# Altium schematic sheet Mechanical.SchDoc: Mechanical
size A4; Date: Not used; ApprovedBy: Not used; CheckedBy: Not used; Author: Not used; CompanyName: STMicroelectronics; DrawnBy: Not used; Engineer: Not used; Organization: Not used; Address1: Not used; Address2: Not used; Address3: Not used; Address4: Not used; DocumentNumber: Not used; Revision: Not used; SheetNumber: 7; SheetTotal: 7
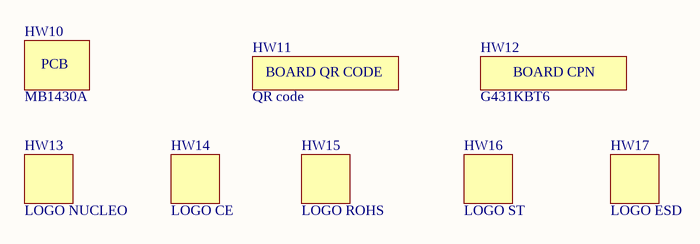
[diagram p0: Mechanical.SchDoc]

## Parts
HW10  value MB1430A  (mechanical)
HW11  value QR code  [STICKER_BOARD-QR-CODE_9X9]  (hidden comment: STICKER_BOARD-QR-CODE)  (mechanical)
HW12  value G431KBT6  [STICKER_BOARD-CPN_13X3]  (hidden comment: STICKER_BOARD_CPN)  (mechanical)
HW13  value LOGO NUCLEO  [LOGO_NUCLEO]  (no BOM)
HW14  value LOGO CE  [LOGO_CE]  (no BOM)
HW15  value LOGO ROHS  [LOGO_ROHS]  (no BOM)
HW16  value LOGO ST  [LOGO_ST]  (no BOM)
HW17  value LOGO ESD  [LOGO_MAIN_1]  (no BOM)

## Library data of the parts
HW10 = MCD-00216: PCB, xxxx for PCB number, Y for PCB revision; Part_Type: Mechanical; Provided_By: SUBCO; Initial_Board_Reference: MB1319
HW11 = MCD-01471: Sticker to mention QR code on small board size (ie Nucleo-32); Part_Type: Mechanical; Provided_By: SUBCO; Initial_Board_Reference: MB1430
HW12 = MCD-01470: Small sticker to mention board CPN (6 digits CPN + last ones FG); Part_Type: Mechanical; Provided_By: SUBCO; Initial_Board_Reference: MB1430
HW13 = MCD-00636: NUCLEO logo footprint for PCB; Part_Type: Mechanical; Initial_Board_Reference: MB1331
HW14 = MCD-00626: CE logo footprint for PCB; Part_Type: Mechanical; Initial_Board_Reference: MB1331
HW15 = MCD-00628: ROHS logo footprint for PCB; Part_Type: Mechanical; Initial_Board_Reference: MB1331
HW16 = MCD-00625: STMicroelectronics logo footprint for PCB; Part_Type: Mechanical; Initial_Board_Reference: MB1331
HW17 = MCD-00627: Hand ESD logo footprint for PCB; Part_Type: Mechanical; Initial_Board_Reference: MB1331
